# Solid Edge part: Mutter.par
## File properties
Sűrűség: 0,000 kg/m^3
Pontosság: 0,990
Author: ahadarics
Last saved by: psaghy
Revision: 77
Username: ahadarics
Dokumentum tartalom típus: 0
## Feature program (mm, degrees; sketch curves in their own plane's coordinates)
base feature "unnamed BaseFeature 1"
sketch for "Furat_1" plane through (7, 0, 0) normal (1, 0, 0) x-axis (0, -1, 0)
  hole centre (0, 0) bore radius 5.3235
hole "Furat_1" through  StartChamferOffset = 0.39 mm; StartChamferAngle = 45 deg
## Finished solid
Body 1: solid body, 23 faces, 47 edges, 26 vertices.
  Faces by surface: cone 14, plane 8, cylinder 1
  Edges by curve: spline 24, circle 16, line 7
Bounding box of the edges (mm): 7.000 x 21.939 x 19.000, from (0, -10.9697, -9.5) to (7, 10.9697, 9.5).
Cylindrical faces by radius (mm): R5.3235 x1
Conical faces (half-angle, radius in mm at the cone's reference point): 45 deg R5.7135 x1, 60 deg R5.6618 x1, 60 deg R10.2348 x12
Planar faces by outward normal: +x 1, +z 1, -x 1, -z 1, oblique 4
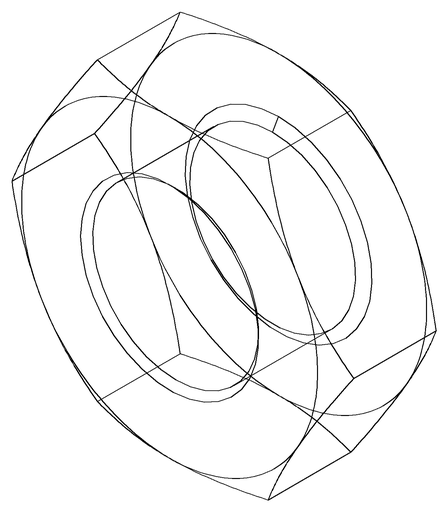
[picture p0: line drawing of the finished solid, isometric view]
